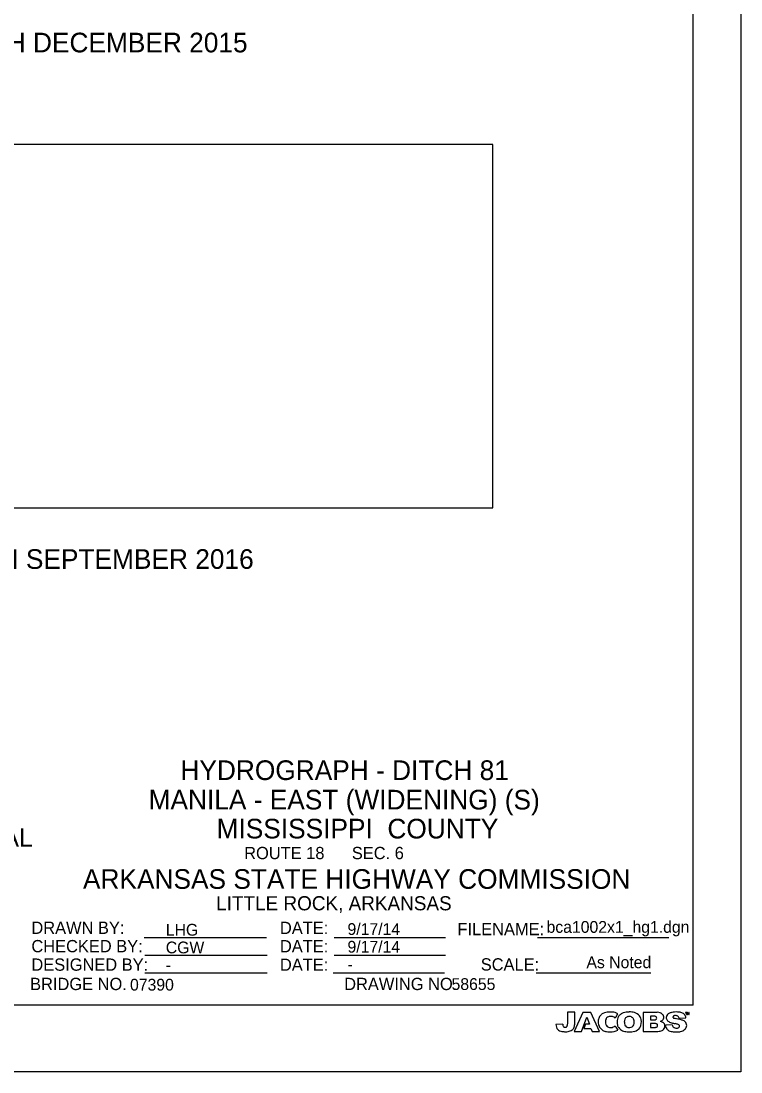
# Model space of a CAD drawing. Extents: x -1063117.8 to -1063083.7, y -253323.4 to -253301.6.
# Drawn here: x -1063090.99 to -1063083.66, y -253323.44 to -253312.74 of the extents above; entities that cross this region are included whole.
import ezdxf

# ---------------------------------------------------------------- set-up
doc = ezdxf.new("R2010")
doc.units = 0
for name, color, linetype in [('B_No_Plot', 7, 'Continuous'), ('border', 7, 'Continuous'), ('Bridge No Ditch 81', 7, 'Continuous'), ('Level 62', 7, 'Continuous'), ('Stamp-ChrisC', 7, 'Continuous'), ('Text', 7, 'Continuous'), ('Title Block Text', 7, 'Continuous'), ('Title Text', 7, 'Continuous')]:
    doc.layers.add(name, color=color, linetype=linetype)

msp = doc.modelspace()

# ---------------------------------------------------------------- linework, layer by layer
at = {"layer": 'B_No_Plot'}
msp.add_lwpolyline([(-1063099.459, -253317.695), (-1063086.185, -253317.695), (-1063086.185, -253313.996), (-1063099.459, -253313.996)], close=True, dxfattribs=at)
at = {"layer": 'border'}
for p, q in [((-1063084.146, -253322.761), (-1063084.146, -253302.216)), ((-1063089.733, -253322.07), (-1063088.49, -253322.07)), ((-1063087.8, -253322.071), (-1063086.666, -253322.071)), ((-1063085.73, -253322.071), (-1063084.394, -253322.071)), ((-1063089.726, -253322.25), (-1063088.483, -253322.25)), ((-1063087.8, -253322.251), (-1063086.666, -253322.251)), ((-1063089.726, -253322.43), (-1063088.483, -253322.43)), ((-1063087.811, -253322.431), (-1063086.677, -253322.431)), ((-1063085.742, -253322.431), (-1063084.577, -253322.431)), ((-1063084.146, -253322.761), (-1063116.157, -253322.761))]:
    msp.add_line(p, q, dxfattribs=at)
for points in [[(-1063085.351, -253322.941), (-1063085.351, -253322.831), (-1063085.425, -253322.831), (-1063085.425, -253322.951)], [(-1063085.228, -253322.883), (-1063085.202, -253322.954), (-1063085.241, -253322.954), (-1063085.257, -253322.996), (-1063085.187, -253322.996), (-1063085.175, -253323.029), (-1063085.098, -253323.029), (-1063085.187, -253322.833), (-1063085.268, -253322.833), (-1063085.358, -253323.029), (-1063085.282, -253323.029), (-1063085.228, -253322.883)], [(-1063084.512, -253322.833), (-1063084.654, -253322.833), (-1063084.654, -253323.029)], [(-1063084.207, -253322.835), (-1063084.222, -253322.835), (-1063084.222, -253322.837), (-1063084.216, -253322.837), (-1063084.216, -253322.854), (-1063084.214, -253322.854), (-1063084.214, -253322.837), (-1063084.207, -253322.837), (-1063084.207, -253322.835)], [(-1063084.203, -253322.838), (-1063084.203, -253322.838), (-1063084.197, -253322.854), (-1063084.195, -253322.854), (-1063084.189, -253322.838), (-1063084.189, -253322.838), (-1063084.189, -253322.854), (-1063084.186, -253322.854), (-1063084.186, -253322.835), (-1063084.19, -253322.835), (-1063084.196, -253322.851), (-1063084.202, -253322.835), (-1063084.205, -253322.835), (-1063084.205, -253322.854), (-1063084.203, -253322.854), (-1063084.203, -253322.838)], [(-1063085.473, -253322.952), (-1063085.543, -253322.956)], [(-1063084.547, -253322.872), (-1063084.58, -253322.872), (-1063084.58, -253322.909)], [(-1063084.58, -253322.909), (-1063084.545, -253322.909)], [(-1063084.542, -253322.947), (-1063084.58, -253322.947), (-1063084.58, -253322.987)], [(-1063084.289, -253322.891), (-1063084.219, -253322.888)], [(-1063084.654, -253323.029), (-1063084.526, -253323.029)], [(-1063084.58, -253322.987), (-1063084.542, -253322.987)], [(-1063084.358, -253322.96), (-1063084.428, -253322.964)]]:
    msp.add_lwpolyline(points, dxfattribs=at)
for centre, radius, start, end in [((-1063085.009, -253322.944), 0.114, 94.7853, 126.8513), ((-1063084.989, -253323.193), 0.363, 86.903, 94.7853), ((-1063084.975, -253322.943), 0.113, 56.9246, 86.903), ((-1063084.689, -253323.008), 0.276, 144.635, 154.8844), ((-1063084.804, -253322.971), 0.142, 111.7104, 123.8806), ((-1063084.816, -253322.94), 0.109, 96.5371, 111.7104), ((-1063084.785, -253323.213), 0.384, 91.9058, 96.5371), ((-1063084.791, -253322.995), 0.166, 73.4477, 92.4253), ((-1063084.775, -253322.943), 0.112, 41.1934, 73.4477), ((-1063084.512, -253322.936), 0.104, 72.1885, 90.1477), ((-1063084.499, -253322.895), 0.0603, 61.4844, 72.1885), ((-1063084.497, -253322.892), 0.0564, 34.7868, 61.4844), ((-1063084.372, -253322.888), 0.0476, 124.08, 177.6485), ((-1063084.341, -253322.934), 0.103, 108.2808, 124.08), ((-1063084.347, -253322.913), 0.0811, 99.8173, 108.2808), ((-1063084.32, -253323.072), 0.242, 93.402, 99.8173), ((-1063084.319, -253323.083), 0.254, 80.6549, 93.402), ((-1063084.293, -253322.921), 0.0897, 57.5906, 80.6549), ((-1063084.271, -253322.887), 0.0494, 39.0736, 57.5906), ((-1063085.421, -253322.946), 0.123, 184.5698, 198.1069), ((-1063085.412, -253322.954), 0.0602, 178.2556, 191.4961), ((-1063085.504, -253322.952), 0.0792, 349.1575, 360), ((-1063085.475, -253322.945), 0.124, 351.3706, 1.8291), ((-1063085.013, -253322.926), 0.0987, 155.2444, 178.6811), ((-1063084.959, -253322.927), 0.153, 178.6811, 194.3912), ((-1063085.029, -253322.918), 0.0809, 126.8513, 155.2444), ((-1063084.934, -253322.933), 0.104, 161.2834, 178.6702), ((-1063084.953, -253322.933), 0.0855, 178.6702, 195.8531), ((-1063084.994, -253322.945), 0.0421, 195.8531, 214.5369), ((-1063085.01, -253322.908), 0.0243, 134.3139, 161.2834), ((-1063084.988, -253322.93), 0.0556, 110.7655, 134.3139), ((-1063084.989, -253322.928), 0.0529, 91.5073, 110.7655), ((-1063084.987, -253322.99), 0.116, 82.6359, 91.5073), ((-1063084.979, -253322.924), 0.0493, 65.5548, 82.6359), ((-1063085.007, -253322.988), 0.119, 54.6002, 65.5548), ((-1063084.82, -253322.928), 0.1, 148.6249, 181.2859), ((-1063084.768, -253322.927), 0.152, 181.2859, 193.1956), ((-1063084.841, -253322.915), 0.0755, 123.8806, 148.6249), ((-1063084.755, -253322.931), 0.0917, 160.8611, 181.2981), ((-1063084.751, -253322.931), 0.0951, 181.2981, 197.9492), ((-1063084.814, -253322.91), 0.0287, 136.1177, 160.8611), ((-1063084.798, -253322.926), 0.0518, 117.7176, 136.1177), ((-1063084.804, -253322.914), 0.0382, 100.2108, 117.7176), ((-1063084.795, -253322.965), 0.0895, 90.9675, 100.2108), ((-1063084.796, -253322.937), 0.0622, 67.077, 90.4218), ((-1063084.787, -253322.916), 0.0386, 24.6274, 67.077), ((-1063084.803, -253322.923), 0.056, 2.7442, 24.6274), ((-1063084.837, -253322.932), 0.091, 342.4003, 0.0845), ((-1063084.996, -253322.932), 0.249, 0.0845, 2.7442), ((-1063084.735, -253322.908), 0.0579, 18.6966, 41.1934), ((-1063084.803, -253322.931), 0.13, 344.5708, 18.6966), ((-1063084.549, -253323.007), 0.135, 86.2098, 89.3498), ((-1063084.545, -253322.846), 0.0633, 270.0363, 284.1438), ((-1063084.547, -253323.194), 0.247, 86.6838, 88.8756), ((-1063084.543, -253322.924), 0.0514, 74.8723, 86.2098), ((-1063084.536, -253322.997), 0.0497, 75.9314, 86.6838), ((-1063084.535, -253322.893), 0.0196, 40.2425, 74.8723), ((-1063084.535, -253322.888), 0.0196, 284.1438, 307.8865), ((-1063084.532, -253322.892), 0.0149, 307.8866, 341.4625), ((-1063084.531, -253322.98), 0.0328, 59.6202, 75.9314), ((-1063084.528, -253322.887), 0.0108, 21.9604, 40.2425), ((-1063084.536, -253322.891), 0.0195, 341.4625, 21.9604), ((-1063084.522, -253322.965), 0.015, 30.8341, 59.6202), ((-1063084.525, -253322.966), 0.0177, 337.5037, 30.8341), ((-1063084.502, -253322.851), 0.0753, 284.6785, 296.8411), ((-1063084.499, -253323.015), 0.092, 61.0815, 79.9242), ((-1063084.489, -253322.877), 0.0471, 296.8412, 329.8182), ((-1063084.474, -253322.968), 0.039, 44.9773, 61.0815), ((-1063084.476, -253322.877), 0.0315, 16.9455, 34.7868), ((-1063084.475, -253322.885), 0.0307, 329.8182, 347.0949), ((-1063084.49, -253322.881), 0.0455, 347.0949, 16.9455), ((-1063084.478, -253322.973), 0.0452, 342.9845, 44.9773), ((-1063084.378, -253322.887), 0.0416, 177.6485, 218.8535), ((-1063084.366, -253322.878), 0.0566, 218.8535, 233.6549), ((-1063084.352, -253322.859), 0.0797, 233.6549, 244.7689), ((-1063084.32, -253322.79), 0.156, 244.7689, 253.473), ((-1063084.272, -253322.63), 0.323, 253.473, 259.8297), ((-1063084.335, -253322.883), 0.016, 146.4706, 165.3108), ((-1063084.343, -253322.881), 0.00815, 165.3108, 208.2887), ((-1063084.336, -253322.876), 0.0169, 211.7417, 226.6339), ((-1063084.341, -253322.879), 0.00877, 130.7855, 146.4706), ((-1063084.331, -253322.892), 0.0256, 97.3055, 130.7855), ((-1063084.338, -253322.878), 0.0145, 226.6339, 245.1429), ((-1063084.321, -253322.841), 0.0549, 245.1429, 260.9806), ((-1063084.325, -253322.935), 0.0692, 81.3212, 97.3055), ((-1063084.404, -253323.369), 0.479, 77.5139, 80.9806), ((-1063084.382, -253323.24), 0.297, 76.0104, 79.8297), ((-1063084.32, -253322.902), 0.0359, 57.474, 81.3212), ((-1063084.334, -253323.047), 0.0974, 67.9593, 76.0104), ((-1063084.312, -253322.889), 0.0202, 37.1977, 57.474), ((-1063084.728, -253324.831), 1.977, 76.8035, 77.5139), ((-1063084.307, -253322.981), 0.0265, 39.9313, 67.9593), ((-1063084.323, -253322.898), 0.0351, 11.0051, 37.1977), ((-1063084.314, -253323.065), 0.163, 65.6998, 76.8035), ((-1063084.279, -253322.987), 0.0776, 51.3565, 65.6998), ((-1063084.28, -253322.895), 0.0612, 6.4385, 39.0736), ((-1063084.263, -253322.967), 0.0523, 36.5162, 51.3565), ((-1063084.26, -253322.965), 0.0486, 345.1611, 36.5162), ((-1063085.488, -253322.968), 0.0527, 198.1069, 225.9799), ((-1063085.469, -253322.949), 0.0797, 225.9799, 261.0714), ((-1063085.444, -253322.786), 0.244, 261.0714, 269.9405), ((-1063085.444, -253322.961), 0.0277, 191.4961, 218.7511), ((-1063085.453, -253322.968), 0.0164, 218.7511, 257.488), ((-1063085.449, -253322.95), 0.0345, 257.488, 275.7834), ((-1063085.448, -253322.959), 0.0257, 275.7834, 301.6926), ((-1063085.444, -253322.863), 0.167, 269.9405, 279.1616), ((-1063085.441, -253322.97), 0.0122, 301.6926, 325.4171), ((-1063085.455, -253322.961), 0.0285, 325.4171, 349.1575), ((-1063085.432, -253322.936), 0.0931, 279.1616, 305.8646), ((-1063085.412, -253322.964), 0.0585, 305.8646, 338.7843), ((-1063085.406, -253322.966), 0.0527, 338.7843, 350.0951), ((-1063085.895, -253322.881), 0.549, 350.0951, 351.3706), ((-1063085.05, -253322.95), 0.0582, 194.3912, 214.1799), ((-1063084.994, -253322.912), 0.127, 214.1799, 231.6615), ((-1063085.025, -253322.951), 0.0765, 231.6616, 258.686), ((-1063084.981, -253322.734), 0.298, 258.686, 268.8163), ((-1063084.997, -253322.946), 0.0388, 214.5369, 253.1918), ((-1063084.986, -253322.91), 0.0769, 253.1918, 291.1956), ((-1063084.985, -253322.886), 0.146, 268.8163, 299.3878), ((-1063084.992, -253322.895), 0.0928, 291.1956, 305.5144), ((-1063084.575, -253322.788), 0.407, 206.7197, 213.678), ((-1063084.85, -253322.946), 0.0683, 193.1956, 217.7499), ((-1063084.816, -253322.92), 0.111, 217.7499, 244.1703), ((-1063084.827, -253322.943), 0.0859, 244.1703, 259.4942), ((-1063084.788, -253322.733), 0.299, 259.4942, 268.6426), ((-1063084.814, -253322.951), 0.0299, 197.9492, 222.7741), ((-1063084.801, -253322.939), 0.0474, 222.7741, 250.1955), ((-1063084.8, -253322.936), 0.0507, 250.1955, 269.1264), ((-1063084.797, -253322.795), 0.191, 269.1264, 272.0424), ((-1063084.791, -253322.852), 0.18, 268.6426, 285.9017), ((-1063084.792, -253322.935), 0.0512, 272.0424, 299.5401), ((-1063084.785, -253322.949), 0.036, 299.5401, 342.4003), ((-1063084.769, -253322.929), 0.101, 285.9017, 322.6714), ((-1063084.745, -253322.947), 0.0698, 322.6714, 344.5708), ((-1063084.542, -253322.883), 0.104, 270.0001, 276.6749), ((-1063084.535, -253322.943), 0.043, 276.6749, 293.0645), ((-1063084.537, -253322.691), 0.338, 271.7224, 279.6279), ((-1063084.525, -253322.966), 0.0178, 293.0645, 337.5037), ((-1063084.49, -253322.964), 0.0609, 279.6279, 313.6357), ((-1063084.484, -253322.971), 0.0511, 313.6357, 342.9845), ((-1063084.052, -253322.911), 0.38, 187.9971, 189.0947), ((-1063084.378, -253322.963), 0.0503, 189.0947, 202.464), ((-1063084.343, -253322.949), 0.0881, 202.464, 215.8926), ((-1063084.364, -253322.964), 0.0621, 215.8926, 243.2968), ((-1063084.351, -253322.939), 0.0904, 243.2968, 257.4598), ((-1063084.324, -253322.819), 0.213, 257.4598, 268.8656), ((-1063084.306, -253322.952), 0.0523, 188.5141, 201.638), ((-1063084.325, -253322.96), 0.0319, 201.638, 242.3635), ((-1063084.319, -253322.948), 0.045, 242.3635, 264.6229), ((-1063084.317, -253322.451), 0.581, 268.8656, 270.7612), ((-1063084.316, -253322.913), 0.0806, 264.6229, 273.901), ((-1063084.314, -253322.947), 0.0464, 273.901, 289.1925), ((-1063084.312, -253322.855), 0.177, 270.7612, 282.5001), ((-1063084.307, -253322.966), 0.0263, 289.1925, 322.566), ((-1063084.298, -253322.973), 0.0145, 2.1813, 39.9313), ((-1063084.297, -253322.973), 0.0141, 322.566, 2.1813), ((-1063084.297, -253322.921), 0.109, 282.5001, 295.6144), ((-1063084.283, -253322.95), 0.0772, 295.6144, 314.022), ((-1063084.272, -253322.962), 0.0608, 314.022, 345.1611)]:
    msp.add_arc(centre, radius, start, end, dxfattribs=at)
at = {"layer": 'Level 62'}
msp.add_lwpolyline([(-1063117.777, -253301.63), (-1063083.659, -253301.63), (-1063083.659, -253323.44), (-1063117.777, -253323.44)], close=True, dxfattribs=at)

# ---------------------------------------------------------------- texts
at = {"layer": 'Bridge No Ditch 81'}
msp.add_text('07390', height=0.12, dxfattribs=at).set_placement((-1063089.878, -253322.611))
at = {"layer": 'Stamp-ChrisC'}
msp.add_text('PROFESSIONAL', height=0.1875, dxfattribs=at).set_placement((-1063092.819, -253321.147))
at = {"layer": 'Text'}
for s, height, p in [('DRAWN BY:', 0.125, (-1063090.882, -253322.034)), ('LHG', 0.12, (-1063089.514, -253322.052)), ('DATE:', 0.125, (-1063088.352, -253322.035)), ('9/17/14', 0.12, (-1063087.664, -253322.045)), ('FILENAME:', 0.125, (-1063086.545, -253322.047)), ('CHECKED BY:', 0.125, (-1063090.882, -253322.221)), ('DATE:', 0.125, (-1063088.352, -253322.222)), ('9/17/14', 0.12, (-1063087.664, -253322.225)), ('CGW', 0.12, (-1063089.514, -253322.232)), ('DESIGNED BY:', 0.125, (-1063090.882, -253322.409)), ('DATE:', 0.125, (-1063088.352, -253322.41)), ('SCALE:', 0.125, (-1063086.308, -253322.407)), ('As Noted', 0.12, (-1063085.232, -253322.383)), ('-', 0.12, (-1063089.514, -253322.412)), ('-', 0.12, (-1063087.664, -253322.405)), ('BRIDGE NO.', 0.125, (-1063090.895, -253322.606)), ('DRAWING NO.', 0.125, (-1063087.698, -253322.606))]:
    msp.add_text(s, height=height, dxfattribs=at).set_placement(p)
at = {"layer": 'Title Block Text'}
for s, p in [('bca1002x1_hg1.dgn', (-1063085.638, -253322.023)), ('58655', (-1063086.605, -253322.605))]:
    msp.add_text(s, height=0.12, dxfattribs=at).set_placement(p)
at = {"layer": 'Title Text'}
for s, height, p in [(' DAILY ELEVATIONS FOR JANUARY THROUGH DECEMBER 2015 ', 0.2, (-1063096.929, -253313.058)), (' DAILY ELEVATIONS FOR JANUARY THROUGH SEPTEMBER 2016 ', 0.2, (-1063097.001, -253318.317)), ('HYDROGRAPH - DITCH 81', 0.2, (-1063089.365, -253320.467)), ('MANILA - EAST (WIDENING) (S)', 0.2, (-1063089.689, -253320.767)), ('MISSISSIPPI  COUNTY', 0.2, (-1063088.997, -253321.062)), ('ROUTE 18      SEC. 6', 0.125, (-1063088.716, -253321.273)), ('ARKANSAS STATE HIGHWAY COMMISSION', 0.2, (-1063090.357, -253321.575)), ('LITTLE ROCK, ARKANSAS', 0.144, (-1063089.001, -253321.794))]:
    msp.add_text(s, height=height, dxfattribs=at).set_placement(p)

doc.saveas('drawing.dxf')
